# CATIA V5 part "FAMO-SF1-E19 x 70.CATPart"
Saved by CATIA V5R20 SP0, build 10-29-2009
Part number: FAMO-SF1-E19 x 70
Definition: NONE
Nomenclature: FAMO-SF1-E19 x 70
Source: Unknown
Description: FAMO-SF1-E19 x 70
Bounding box of the stored display mesh (mm): x -52 to 18, y -17 to 17, z -17 to 17
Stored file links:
  C:\Users\Utente\Desktop\IO LAVORO\3D X SITO CF\X SITO\FAMO\FAMO-SF1-E19 x 70.CATPart

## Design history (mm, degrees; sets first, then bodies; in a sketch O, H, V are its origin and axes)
Body1 "FAMO-SF1-E19 x 70" (main body)
  Solid1: solid without history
